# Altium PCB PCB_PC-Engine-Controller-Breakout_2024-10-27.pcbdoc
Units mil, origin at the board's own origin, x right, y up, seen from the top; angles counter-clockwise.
Board outline 1955 x 1756.47 mil, 2 copper layers (Top Layer, Bottom Layer); 2 components, 9 nets, 17 pads, 1 vias.
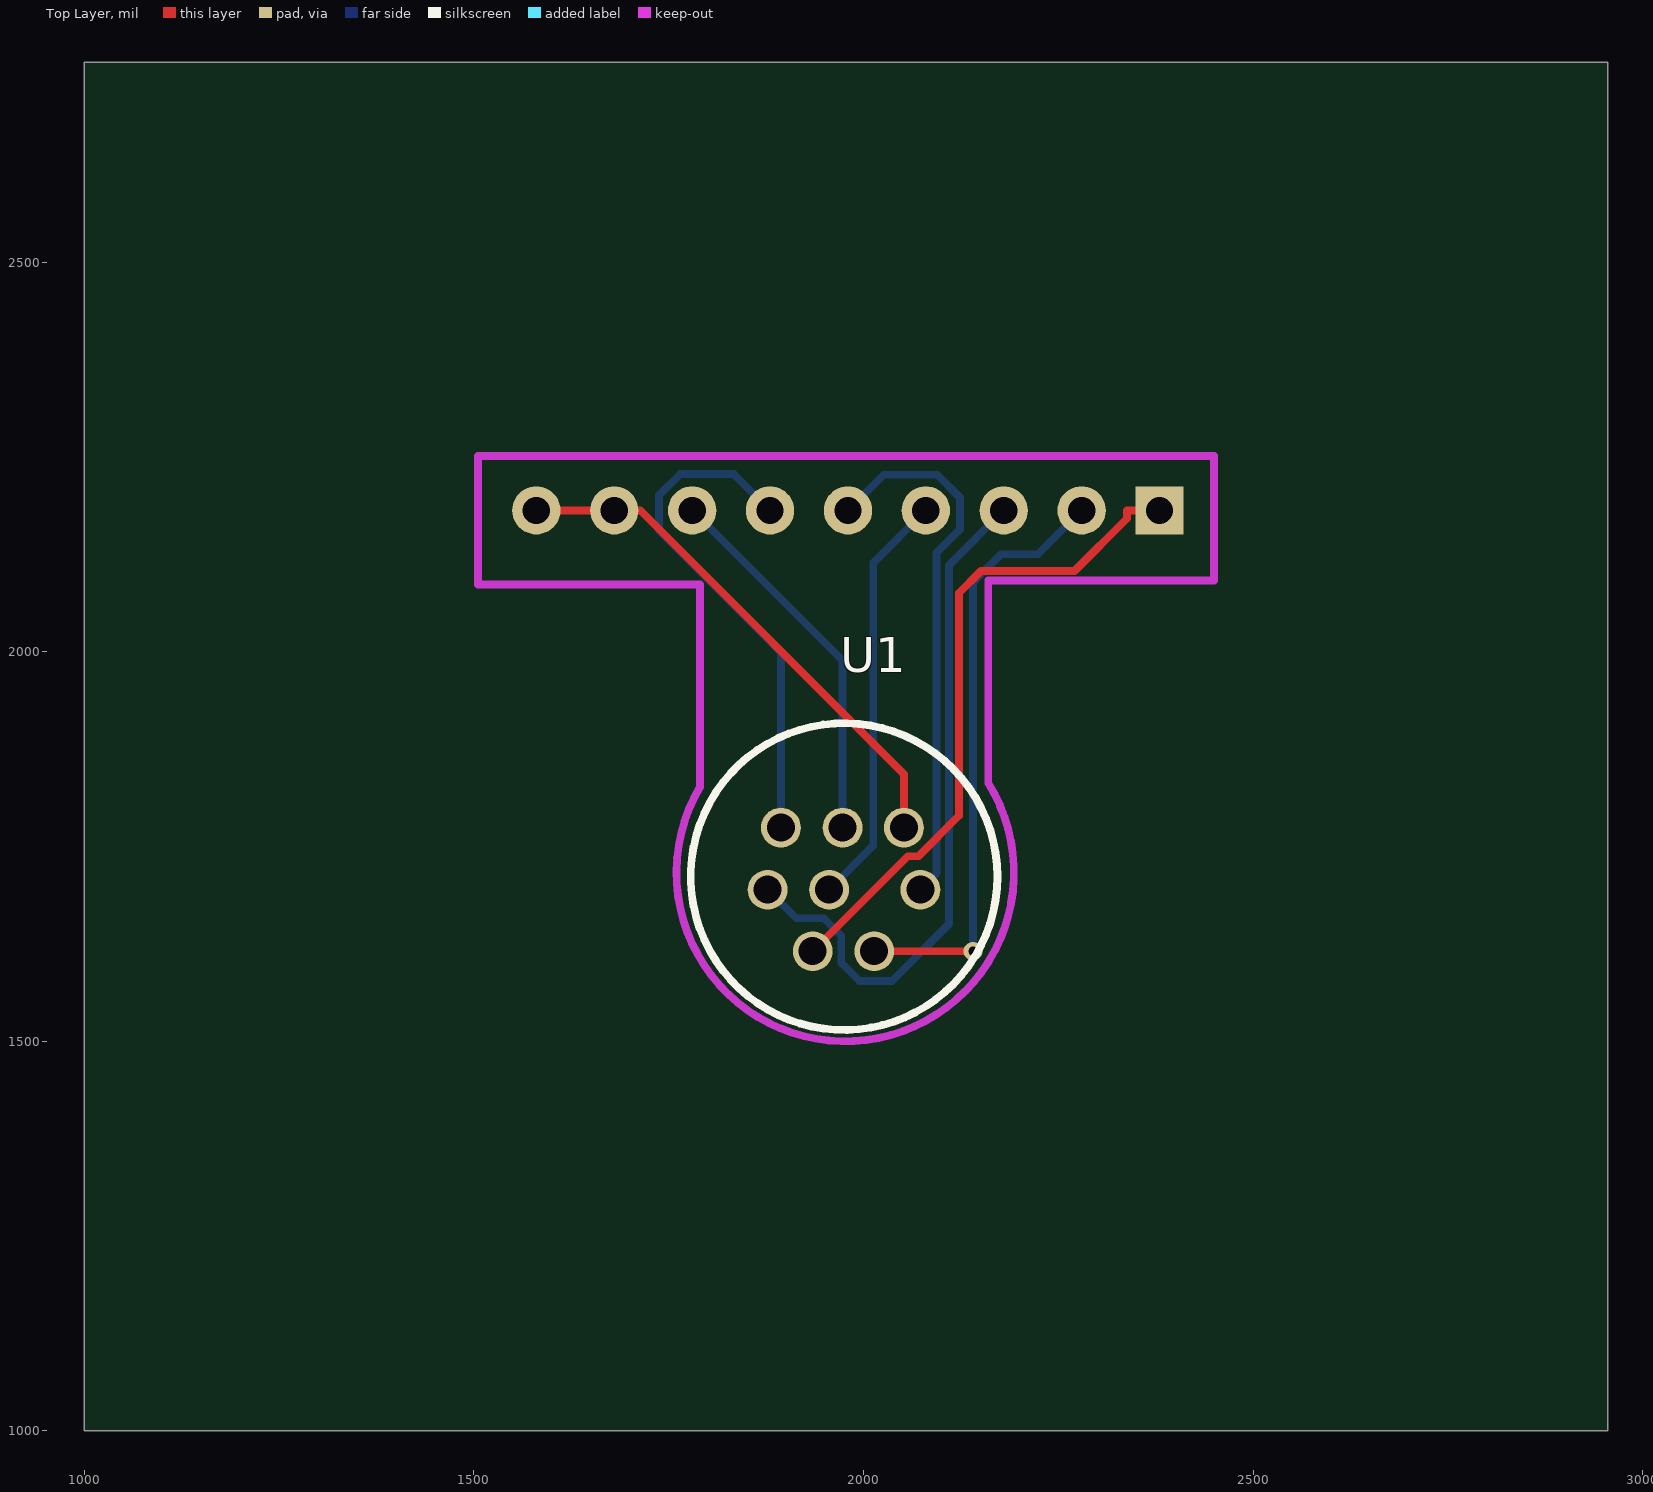
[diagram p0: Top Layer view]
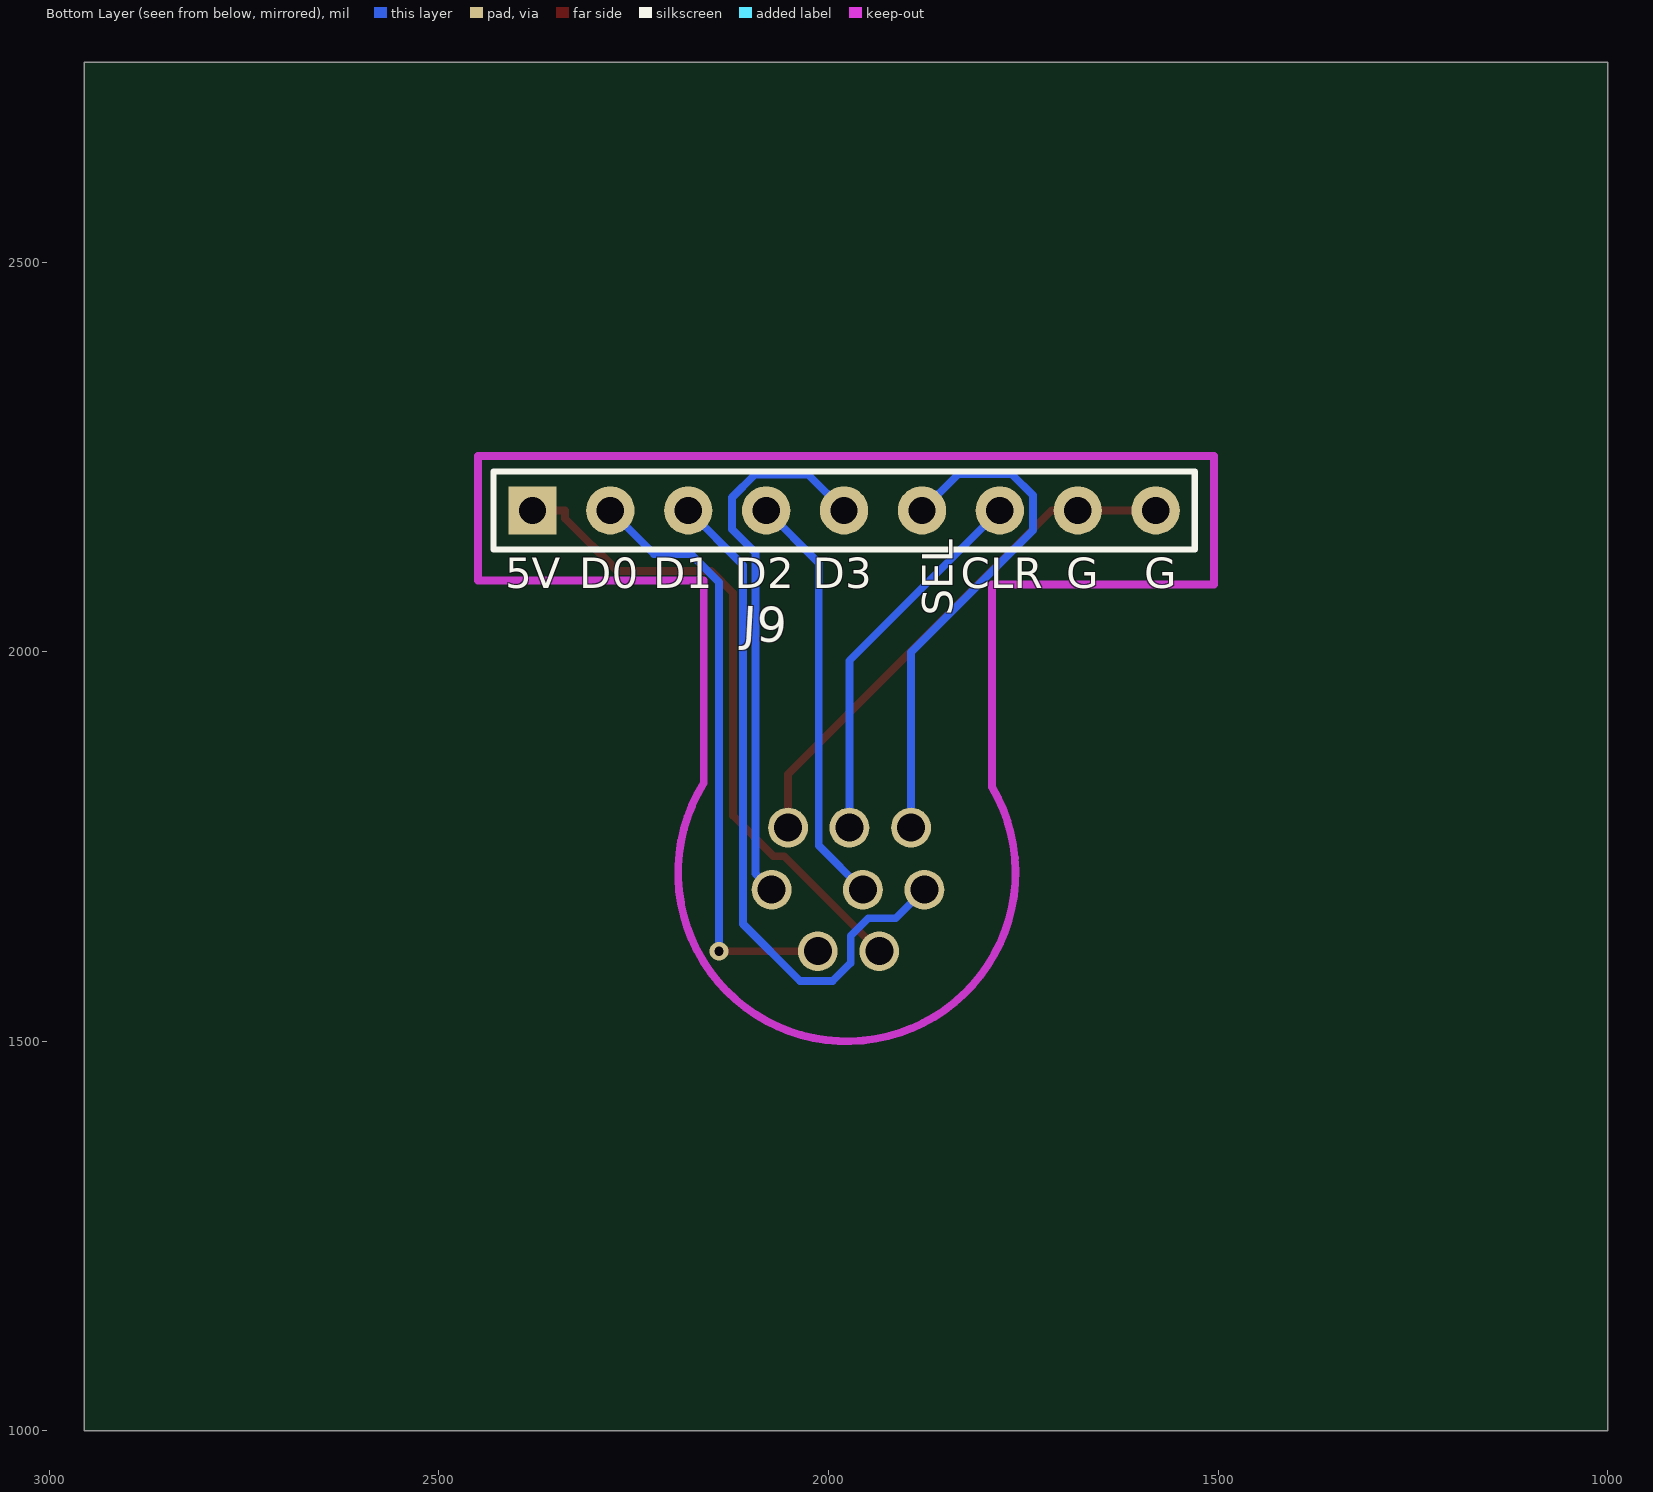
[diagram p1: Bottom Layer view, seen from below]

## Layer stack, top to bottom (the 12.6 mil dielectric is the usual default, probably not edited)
Top Layer: signal copper (thickness not stored)
Dielectric: dielectric 12.6, FR-4, Dk 4.8
Bottom Layer: signal copper (thickness not stored)

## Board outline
2955,1000 1000,1000 1000,2756.47 2955,2756.47

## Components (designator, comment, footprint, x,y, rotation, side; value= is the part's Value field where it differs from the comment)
J9 "CONNECTOR" HDR-M-2.54_1X9 1980,2181.47 r0 bottom
U1 "PC Engine Controller Breakout" "PC ENGINE CONTROLLER BREAKOUT" 1970,1716.47 r0 top

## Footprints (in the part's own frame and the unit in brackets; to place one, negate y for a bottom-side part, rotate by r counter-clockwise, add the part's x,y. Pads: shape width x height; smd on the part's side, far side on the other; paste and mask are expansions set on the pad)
HDR-M-2.54_1X9 [mil]
  rect 62x62 hole 35 paste+0 mask+2: 1(400,0)
  round 62 hole 35 paste+0 mask+2: 2(300,0) 3(200,0) 4(100,0) 5(0,0) 6(-100,0) 7(-200,0) 8(-300,0) 9(-400,0)
  silkscreen extent -450,-50 450,50
"PC ENGINE CONTROLLER BREAKOUT" [mm]
  round 1.3 hole 0.914 paste+0 mask+0.051: 1(-0.895,-2.56) 2(1.11,-2.56) 3(-2.365,-0.555) 4(-0.36,-0.555) 5(2.615,-0.555) 6(-1.93,1.47) 7(0.08,1.47) 8(2.08,1.47)
  silkscreen extent -4.87,-5.13 5.13,4.87

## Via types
v1: diameter 24.02, hole 12.01, Top Layer to Bottom Layer, tented both sides, 1 vias

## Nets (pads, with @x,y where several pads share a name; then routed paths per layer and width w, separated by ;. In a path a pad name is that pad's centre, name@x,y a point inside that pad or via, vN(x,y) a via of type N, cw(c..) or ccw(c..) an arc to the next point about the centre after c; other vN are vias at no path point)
+5V: J9.1 U1.1 | length 853.2
  Top Layer w10: U1.1 2056.77,1737.69 2070.59,1737.69 2122.39,1789.49 2122.39,2075.34 2150.85,2103.8 2270.84,2103.8 2338.01,2170.97 2338.01,2181.47 J9.1
CLR: J9.7 U1.7 | length 487.1
  Bottom Layer w10: J9.7 1973.15,1988.32 U1.7
D0: J9.2 U1.2 | length 778.1
  Top Layer w10: U1.2 v1(2140.46,1615.68)
  Bottom Layer w10: v1(2140.46,1615.68) 2140.46,2089.34 2176.38,2125.26 2223.79,2125.26 J9.2
D1: J9.3 U1.3 | length 891.9
  Bottom Layer w10: U1.3 1913.54,1657.97 1949.06,1657.97 1971.41,1635.62 1971.41,1600.7 1994.47,1577.64 2036.72,1577.64 2109.67,1650.59 2109.67,2111.14 J9.3
D2: J9.4 U1.4 | length 538.3
  Bottom Layer w10: U1.4 2012.58,1751.37 2012.58,2114.05 J9.4
D3: J9.5 U1.5 | length 699.5
  Bottom Layer w10: J9.5 2025.89,2227.36 2094.49,2227.36 2123.85,2198 2123.85,2157.22 2093.61,2126.98 2093.61,1715.28 U1.5
GND: J9.8 J9.9 U1.8 | length 680.7
  Top Layer w10: J9.9 J9.8 1713.33,2181.47 2051.89,1842.91 U1.8
S$1859: 
SEL: J9.6 U1.6 | length 664.4
  Bottom Layer w10: J9.6 1833.38,2228.09 1764.71,2228.09 1737.54,2200.92 1737.54,2155.99 1894.02,1999.51 U1.6

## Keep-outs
Keep-Out Layer:
  lines w10 net S$1859: 1789.93,1826.47 ccw(c1976.49,1716.54) 2160,1831.47

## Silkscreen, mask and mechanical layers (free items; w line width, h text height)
Bottom Overlay:
  text "G" at 1595,2081.78 h39.37
  text "G" at 1695,2081.78 h39.37
  text "CLR" at 1830,2081.78 h39.37
  text "D3" at 2020,2081.78 h39.37
  text "D2" at 2120,2081.78 h39.37
  text "D1" at 2225,2081.78 h39.37
  text "D0" at 2320,2081.78 h39.37
  text "5V" at 2415,2081.78 h39.37
  text "SEL" at 1840.32,2046.47 h39.37 r270
Document:
  lines w0.1: 1977.49,1878.22 1977.51,1878.24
